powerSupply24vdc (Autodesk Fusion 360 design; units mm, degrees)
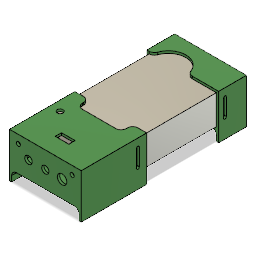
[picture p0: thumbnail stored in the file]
sketch "Sketch1" plane through (0, 0, 0) normal (0, 1, 0) x axis (1, 0, 0)
  dimension "d1" = 115
  dimension "d2" = 215
extrude "Extrude1" new body sketch "Sketch1" along normal blind 50.5
sketch "Sketch2" plane through (115, 0, 0) normal (1, 0, 0) x axis (0, 0, -1)
  dimension "d5" = 33
  dimension "d6" = 8
  dimension "d7" = 13
  dimension "d8" = 34.6302
sketch "Sketch3" plane through (0, 50.5, 0) normal (0, 1, 0) x axis (-1, 0, 0)
  dimension "d9" = 48
  dimension "d10" = 37
  dimension "d11" = 60
  dimension "d12" = 28
  dimension "d13" = 20
  dimension "d14" = 34
  dimension "d15" = 73.0154
  dimension "d16" = 18
sketch "Sketch4" plane through (0, 0, 0) normal (-1, 0, 0) x axis (0, 0, 1)
sketch "Sketch1" plane through (0, 0, -215) normal (0, 0, -1) x axis (-1, 0, 0)
  dimension "d17" = 4
extrude "Extrude1" new body sketch "Sketch1" against normal blind 44
extrude "Extrude2" add sketch "Sketch1" along normal blind 4
extrude "Extrude3" cut sketch "Sketch2" along normal blind 13.874
extrude "Extrude4" cut sketch "Sketch4" along normal blind 14.283
sketch "Sketch2" plane through (0, 50.5, 0) normal (0, 1, 0) x axis (-1, 0, 0)
extrude "Extrude5" cut sketch "Sketch2" along normal blind 9.223
fillet "Fillet1" radius 9.162
sketch "Sketch3" plane through (0, 0, -219) normal (0, 0, -1) x axis (-1, 0, 0)
  dimension "d29" = 50.5
  dimension "d30" = 115
  dimension "d31" = 18
  dimension "d32" = 4
extrude "Extrude6" cut sketch "Sketch3" against normal blind 4
extrude "Extrude7" add sketch "Sketch3" against normal blind 48
fillet "Fillet2" radius 8
sketch "Sketch1"
extrude "Extrude1" new body sketch "Sketch1" blind -48
extrude "Extrude2" add sketch "Sketch1" blind 60
sketch "Sketch2" plane through (0, 0, 60) normal (0, 0, 1) x axis (1, 0, 0)
extrude "Extrude3" add sketch "Sketch2" along normal blind 4
extrude "Extrude4" cut sketch "Sketch4" to an object
extrude "Extrude5" cut sketch "Sketch2" to an object
sketch "Sketch3" plane through (0, 54.5, 0) normal (0, 1, 0) x axis (-1, 0, 0)
extrude "Extrude6" cut sketch "Sketch3" against normal blind 4
fillet "Fillet1" radius 9
fillet "Fillet2" radius 9
sketch "Sketch4" plane through (0, 0, 64) normal (0, 0, 1) x axis (1, 0, 0)
  dimension "d52" = 12.3
  dimension "d53" = 7
  dimension "d54" = 12.8
  dimension "d55" = 16.2
extrude "Extrude7" cut sketch "Sketch4" against normal blind 4
sketch "Sketch5" plane through (0, 54.5, 0) normal (0, 1, 0) x axis (-1, 0, 0)
  dimension "d58" = 13
  dimension "d59" = 6
  dimension "d60" = 10
extrude "Extrude8" cut sketch "Sketch5" against normal blind 4
sketch "Sketch6" plane through (0, 0, 60) normal (0, 0, -1) x axis (-1, 0, 0)
  dimension "d63" = 19
  dimension "d64" = 2.4
extrude "Extrude10" cut sketch "Sketch6" against normal blind 1
extrude "Extrude11" cut sketch "Sketch6" against normal blind 1
sketch "Sketch7" plane through (0, -4, 0) normal (0, -1, 0) x axis (1, 0, 0)
  dimension "d71" = 8
sketch "Sketch8" plane through (0, 54.5, 0) normal (0, 1, 0) x axis (-1, 0, 0)
  dimension "d72" = 23.2
  dimension "d73" = 10.7
extrude "Extrude12" cut sketch "Sketch8" against normal blind 4
sketch "Sketch1" plane through (0, 54.5, 0) normal (0, 1, 0) x axis (-1, 0, 0)
  dimension "d76" = 8
extrude "Extrude1" new body sketch "Sketch1" along normal blind 2.4
fillet "Fillet1" radius 8
sketch "Sketch1" plane through (0, 0, 64) normal (0, 0, 1) x axis (1, 0, 0)
  dimension "d80" = 0.2
  dimension "d81" = 5.2
  dimension "d82" = 12
extrude "Extrude1" new body sketch "Sketch1" along normal blind 3
chamfer "Chamfer1" distance 1.5
extrude "Extrude2" add sketch "Sketch1" against normal blind 2
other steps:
create_component "CreateComponent1"
create_component "CreateComponent2"
create_component "CreateComponent3"
create_component "CreateComponent4"
create_component "CreateComponent5"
